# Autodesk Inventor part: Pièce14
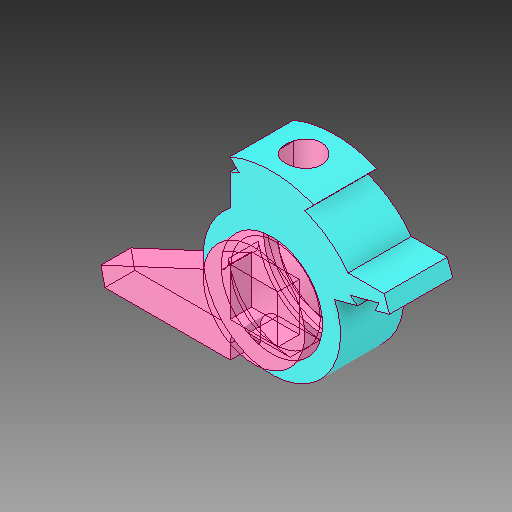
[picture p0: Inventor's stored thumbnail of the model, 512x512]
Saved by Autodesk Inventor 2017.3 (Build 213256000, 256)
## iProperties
Created: 2007-11
Part Number: Pièce14
Material: Générique
Document SubType Name: Modeling
Designer: ficho
Density: 1 g/cm^3
Appearance: Par défaut
Author: ficho
Sending System: SolidWorks 2009
Last Author: christophe
Last Saved: 2011-02-10
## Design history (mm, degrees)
feature "Congé3"
node "Solide1"
